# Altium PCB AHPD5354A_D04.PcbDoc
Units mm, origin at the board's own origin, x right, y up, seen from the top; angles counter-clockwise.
Board outline 70.4 x 70.4 mm, 2 copper layers (Top Layer, Bottom Layer), stack 1.57 mm thick; 18 components, 11 nets, 81 pads, 300 vias.
Unrouted connection lines stored in the file: 6.
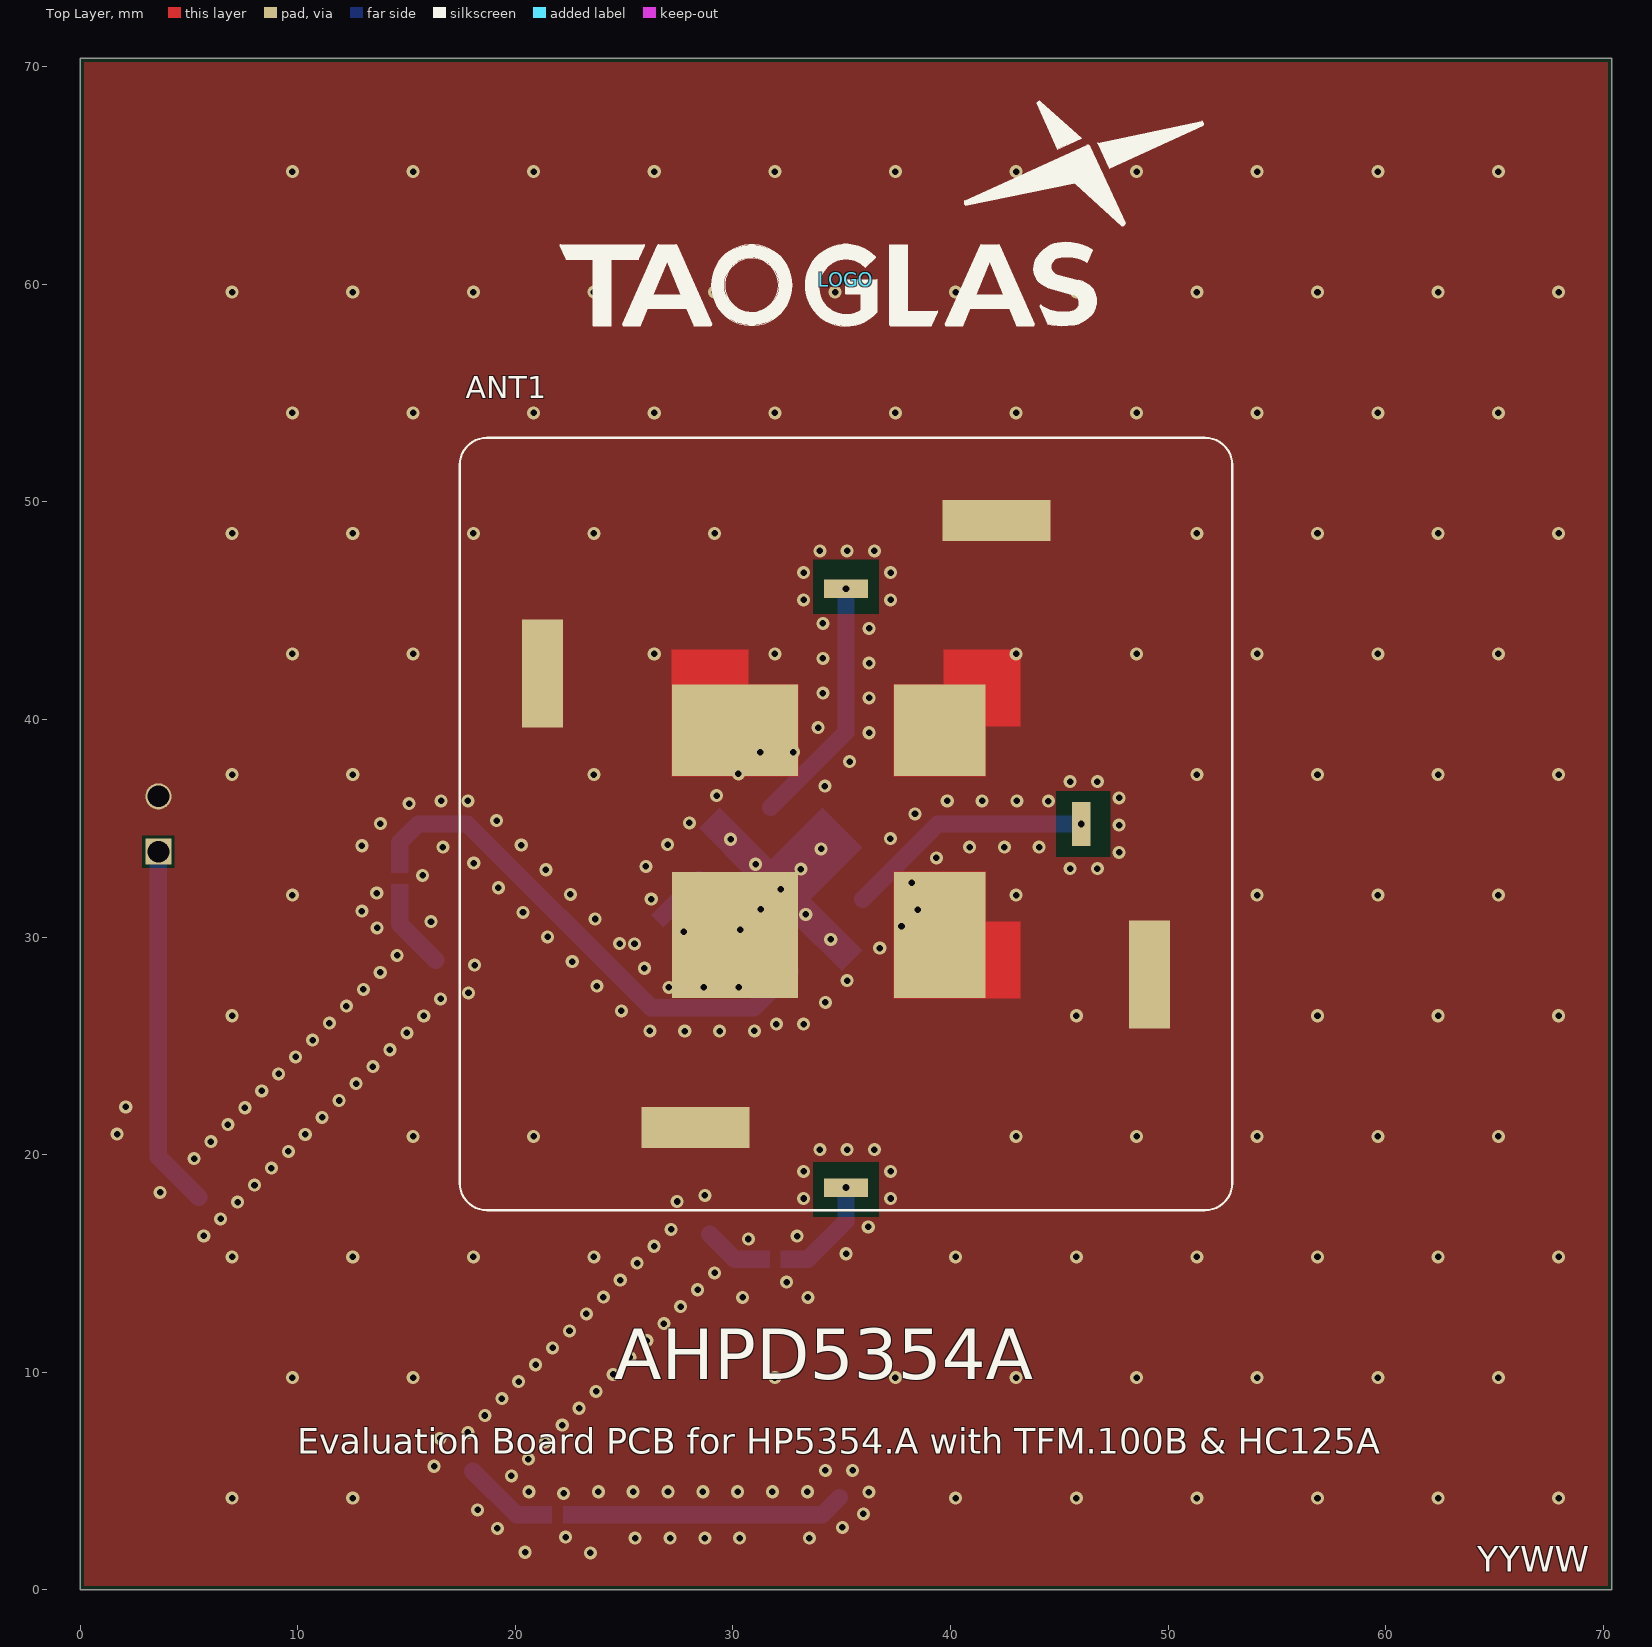
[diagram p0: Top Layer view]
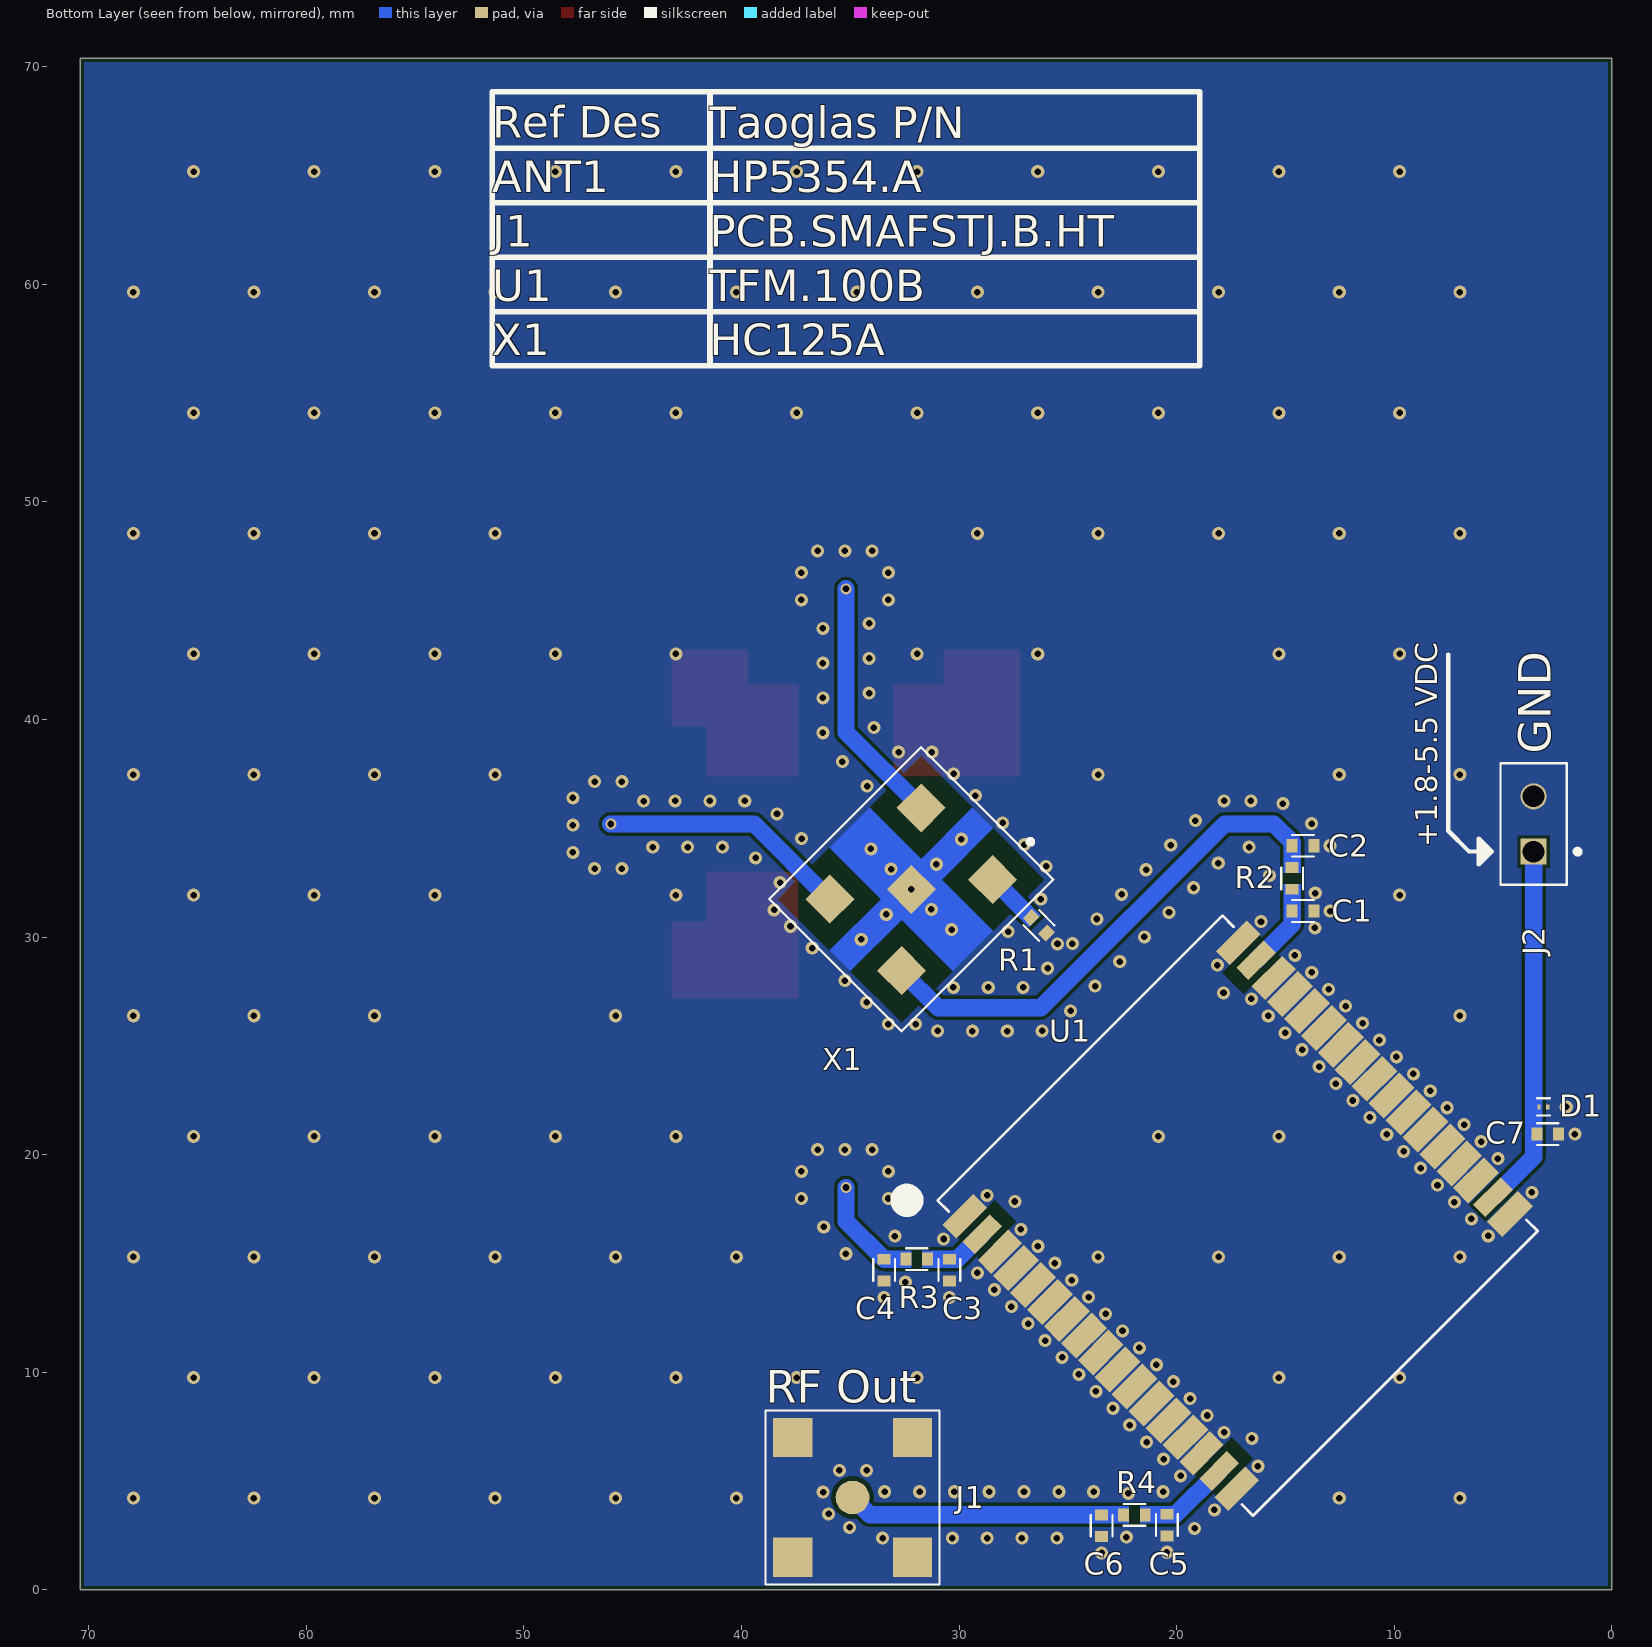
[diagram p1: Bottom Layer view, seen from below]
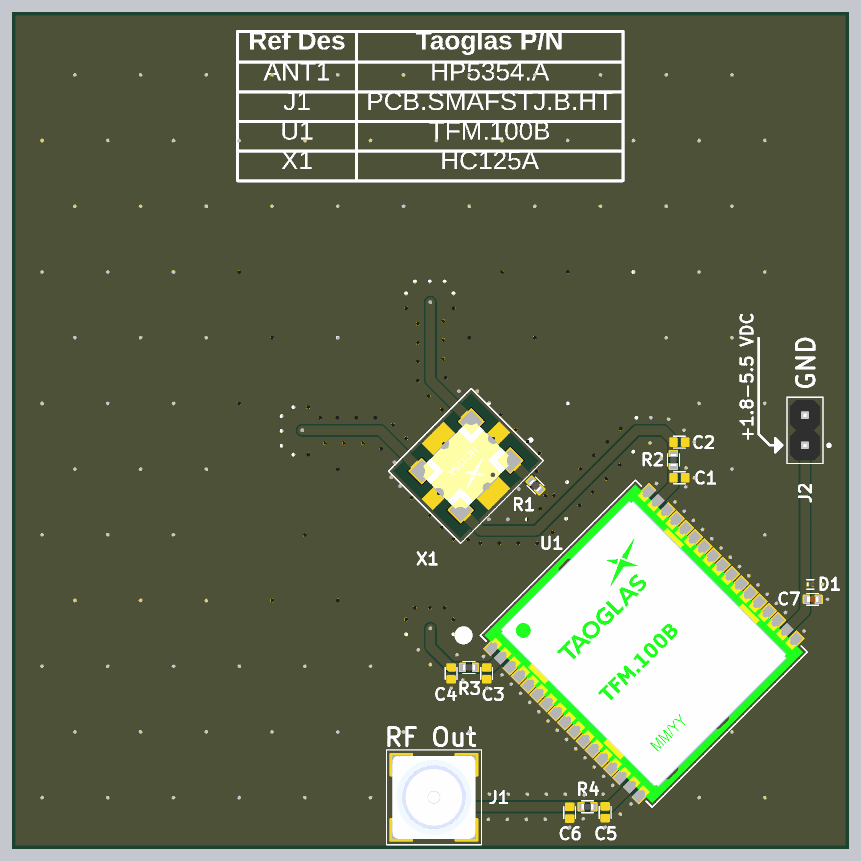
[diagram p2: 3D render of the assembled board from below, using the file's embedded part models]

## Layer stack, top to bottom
Top Solder Mask: solder mask 0.01, Solder Resist, Dk 3.5
Top Layer: signal copper 0.035
Dielectric: core 1.5, FR-4, Dk 4.2
Bottom Layer: signal copper 0.035
Bottom Solder Mask: solder mask 0.01, Solder Resist, Dk 3.5

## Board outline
0,0 70.4,0 70.4,70.4 0,70.4

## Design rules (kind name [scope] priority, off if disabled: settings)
BoardOutlineClearance [All] p1: gap=0.196 ignorepadtopadclearanceinfootprint=FALSE
Clearance Clearance_Polygon [All] p1: gap=0.14 ignorepadtopadclearanceinfootprint=FALSE except(0.05: Arc-Arc Arc-Track Track-Track; 0.1: Arc-SMDPad Arc-THPad Track-SMDPad Track-THPad SMDPad-SMDPad SMDPad-THPad THPad-THPad; 0.2: Arc-Via Arc-Text Arc-Hole Track-Via Track-Text Track-Hole SMDPad-Via SMDPad-Text SMDPad-Hole THPad-Via THPad-Text THPad-Hole Via-Via Via-Text Via-Hole Fill-Text Fill-Hole Poly-Text Poly-Hole Region-Text Region-Hole Text-Text Text-Hole)
HoleSize [All] p1: absolutevalues=TRUE maxlimit=6 minlimit=0.15 maxpercent=80.000 minpercent=20.000
MinimumAnnularRing [All] p1: minimumring=0.1
MinimumSolderMaskSliver [All vs InPadClass('All Pads')] p1: minsoldermaskwidth=0.05
PolygonConnect [All] p1: connectstyle=Direct reliefconductorwidth=0.254 reliefentries=4 polygonreliefangle="90 Angle" airgapwidth=0.254
RoutingVias [All] p1: holewidth=0.3 width=0.8 viastyle="Through Hole" minholewidth=0.15 minwidth=0.65 maxholewidth=6 maxwidth=6.5
SilkToSilkClearance [All] p1: silktosilkclearance=0.1
SilkToSolderMaskClearance [IsPad or IsVia vs OnLayer('Top Overlay')] p1: minsilkscreentomaskgap=0.05 clearancetoexposedcopper=FALSE
SilkToSolderMaskClearance SilkToSolderMaskClearance_1 [IsPad or IsVia vs OnLayer('Bottom Overlay')] p2: minsilkscreentomaskgap=0.05 clearancetoexposedcopper=FALSE
SolderMaskExpansion [Not IsVia] p1: expansion=0.1 istentingtop=FALSE
Width [All] p1: maxlimit=5 minlimit=0.1 preferedwidth=1 minimp=50.000000 maximp=50.000000 favimp=50.000000
26 further rules are at their usual default settings.

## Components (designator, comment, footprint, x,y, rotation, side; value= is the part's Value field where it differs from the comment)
ANT1 "TAOGLAS_HP5354.A" TAOGLAS_HP5354.A 35.2,35.2 r0 top
C1 "DNF" "0402 - DNF" 14.2,31.2 r0 bottom
C2 "DNF" "0402 - DNF" 14.2,34.2 r180 bottom
C3 "DNF" "0402 - DNF" 30.45,14.7 r90 bottom
C4 "DNF" "0402 - DNF" 33.45,14.7 r90 bottom
C5 "DNF" "0402 - DNF" 20.453,2.982 r90 bottom
C6 "DNF" "0402 - DNF" 23.45,2.95 r90 bottom
C7 "Capacitor_Ceramic_1005(0402)_L1_W0.5_H0.5mm_100pF+-5%_50V_-55 to 125C_Murata_GRM1555C1H101JA01" "Capacitor - 0402 - GRM" 2.95,20.95 r0 bottom value=100pF
D1 "ESD245B1W0201E6327XTSA1" "Diode - 0201 (0603 Metric) - DSN0603-2" 3.15,22.2 r180 bottom
J1 "TAOGLAS_PCB.SMAFSTJ.B.HT" TAOGLAS_PCB.SMAFSTJ.B.HT 34.9,4.25 r90 bottom
J2 "PREC002SAAN-RC" SULLINS_PREC002SAAN-RC 3.6,35.2 r90 bottom
LOGO "TAOGLAS_LOGO" "TAOGLAS_LOGO - No R - 10.3mm" 35.2,60.2 r0 top
R1 "Resistor_Thick Film_1005(0402)_49.9Ohms+-1%_0.063W" "Resistor - 0402 - RC_L" 26.335,30.545 r45 bottom value=49.9
R2 "Resistor_Thick Film_1005(0402)_0Ohm" "Resistor - 0402 - RC_L" 14.7,32.7 r90 bottom value=0
R3 "Resistor_Thick Film_1005(0402)_0Ohm" "Resistor - 0402 - RC_L" 31.95,15.2 r0 bottom value=0
R4 "Resistor_Thick Film_1005(0402)_0Ohm" "Resistor - 0402 - RC_L" 21.95,3.45 r180 bottom value=0
U1 "TAOGLAS_TFM.100B" TAOGLAS_TFM.100B 17.2,17.2 r135 bottom
X1 "TAOGLAS_HC125A" TAOGLAS_HC125A 32.2,32.2 r315 bottom

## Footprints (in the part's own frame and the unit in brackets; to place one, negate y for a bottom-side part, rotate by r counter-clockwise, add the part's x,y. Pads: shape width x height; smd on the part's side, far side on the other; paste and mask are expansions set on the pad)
"0402 - DNF" [mm]
  rect 0.5x0.6 smd paste-2539.97 mask+0.1: 1(-0.5,0) 2(0.5,0)
  silkscreen extent -0.5,-0.5 0.5,0.5
"Capacitor - 0402 - GRM" [mm]
  rect 0.5x0.6 smd mask+0.1: 1(-0.5,0) 2(0.5,0)
  silkscreen extent -0.5,-0.5 0.5,0.5, body extent -0.5,-0.25 0.5,0.25, height 0.55
"Diode - 0201 (0603 Metric) - DSN0603-2" [mm]
  rect 0.14x0.24 smd paste-2539.97 mask+0.05: 1(-0.2,0) 2(0.2,0)
  silkscreen extent -0.3,-0.4 0.3,0.4, body extent -0.3,-0.15 0.3,0.15, height 0.32
"Resistor - 0402 - RC_L" [mm]
  rect 0.5x0.6 smd mask+0.1: 1(-0.5,0) 2(0.5,0)
  silkscreen extent -0.5,-0.5 0.5,0.5, body extent -0.5,-0.25 0.5,0.25, height 0.4
SULLINS_PREC002SAAN-RC [mm] "2 Positions Header, 0.100\" (2.54mm)"
  rect 1.2x1.2 hole 1 mask+0.1: 1(-1.27,0)
  round 1.2 hole 1 mask+0.1: 2(1.27,0)
  silkscreen extent -2.79,-1.52 2.79,1.52, body extent -2.54,-1.27 2.54,1.27, height 8.38
TAOGLAS_HC125A [mm] "Low Profile, High Performance Multiband GNSS Hybrid Coupler"
  rect 1.6x1.6 smd paste-0.1 mask+0.1: 1(-2.96,2.325) 2(2.96,2.325) 3(2.96,-2.325) 4(-2.96,-2.325)
  rect 1.6x1.6 smd: 5(0,0)
  Top Layer region: -4.62,0.665 -4.62,-0.665 -1.3,-0.665 -1.3,-3.985 1.3,-3.985 1.3,-0.665 4.62,-0.665 4.62,0.665 1.3,0.665 1.3,3.985 -1.3,3.985 -1.3,0.665
  silkscreen extent -5.51,-4.3 4.94,4.3, body extent -3.17,-2.54 3.18,2.54, height 1.5
TAOGLAS_HP5354.A [mm] "Multi-Band GNSS L1/L5 Patch Antenna"
  rect 2x0.85 smd paste-0.1 mask+0.1: 1(0,10.805) 11(0,-16.705)
  rect 0.85x2 smd paste-0.1 mask+0.1: 2(10.805,0)
  rect 5.8x4.2 smd paste-2539.97 mask+0.1: 3(-5.1,4.3)
  rect 4.2x4.2 smd paste-2539.97 mask+0.1: 4(4.3,4.3)
  rect 5.8x5.8 smd paste-0.1 mask+0: 5(-5.1,-5.1)
  rect 4.2x5.8 smd paste-2539.97 mask+0.1: 6(4.3,-5.1)
  rect 4.95x1.9 smd paste-0.1 mask+0: 7(6.915,13.95) 9(-6.915,-13.95)
  rect 1.9x4.95 smd paste-0.1 mask+0: 8(13.95,-6.915) 10(-13.95,6.915)
  Top Layer region: 2.2,2.2 2.2,6.4 4.5,6.4 4.5,8 8,8 8,4.5 6.4,4.5 6.4,2.2
  Top Layer region: -2.2,2.2 -2.2,6.4 -4.5,6.4 -4.5,8 -8,8 -8,2.2
  Top Layer region: 6.4,-2.2 2.2,-2.2 2.2,-8 8,-8 8,-4.5 6.4,-4.5
  silkscreen extent -17.75,-17.75 17.75,17.75, body extent -17.5,-17.51 17.5,17.5, height 4.02
"TAOGLAS_LOGO - No R - 10.3mm" [mm] "Total Height from bottom of the text to the top of the star is 10.3mm"
  silkscreen extent -13.15,-2.12 16.43,8.2
TAOGLAS_PCB.SMAFSTJ.B.HT [mm] "SMA (F) Surface Mount PCB Jack"
  round 1.55 smd paste-0.1 mask+0.1: 1(0,0)
  rect 1.8x1.8 smd paste-0.1 mask+0.1: 2(-2.75,2.75) 3(2.75,2.75) 4(-2.75,-2.75) 5(2.75,-2.75)
  silkscreen extent -4,-4 4,4, body extent -3.5,-3.5 3.5,3.5, height 10.23
TAOGLAS_TFM.100B [mm] "Surface mount GNSS front-end module covering L1/L5"
  rect 2x0.9 smd paste-2539.97 mask+0: 1(-8.9,8.85) 3(-8.9,6.55) 15(-8.9,-6.55) 17(-8.9,-8.85) 32(8.9,6.55) 34(8.9,8.85)
  rect 1.8x0.8 smd paste-2539.97: 2(-8.9,7.7) 16(-8.9,-7.7) 19(8.9,-7.7) 33(8.9,7.7)
  rect 2x1 smd paste-2539.97 mask+0: 4(-8.9,5.5) 5(-8.9,4.4) 6(-8.9,3.3) 7(-8.9,2.2) 8(-8.9,1.1) 9(-8.9,0) 10(-8.9,-1.1) 11(-8.9,-2.2) 12(-8.9,-3.3) 13(-8.9,-4.4) 14(-8.9,-5.5) 18(8.9,-8.8) 20(8.9,-6.6) 21(8.9,-5.5) 22(8.9,-4.4) 23(8.9,-3.3) 24(8.9,-2.2) 25(8.9,-1.1) 26(8.9,0) 27(8.9,1.1) 28(8.9,2.2) 29(8.9,3.3) 30(8.9,4.4) 31(8.9,5.5)
  silkscreen extent -10.5,-10.25 9.25,11.5, body extent -9,-10 9,10, height 2.74

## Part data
ANT1: library part CMP-364-000001-9, "Low Profile Multi-Band GNSS L1/L5 Patch Antenna", Temp_High=+85C, Temp_Low=-40C
C1 C2 C3 C4 C5 C6: library part CMP-00006-21, "Do Not Fit"
C7: library part CMP-001-00343-45, "100 pF ±5% 50V Ceramic Capacitor C0G, NP0 0402 (1005 Metric)", Max. Operating Temperature=125°C, Min. Operating Temperature=-55°C, Package / Case="0402 (1005 Metric)", Temperature Coefficient="C0G, NP0", Tolerance=±5%, Voltage - Rated=50V
D1: library part CMP-004-00167-10, "7.5V Clamp 5.5A (8/20µs) Ipp Tvs Diode Surface Mount WLL-2-3", Capacitance @ Frequency="5.8pF @ 1GHz", Current - Peak Pulse (10/1000µs)="5.5A (8/20µs)", Max. Operating Temperature=125°C, Max. Voltage - Clamping @ Ipp=7.5V, Min. Operating Temperature=-55°C, Package / Case="0201 (0603 Metric)", Power - Peak Pulse=44W, Power Line Protection=No, Supplier Device Package=WLL-2-3, Voltage - Reverse Standoff (Typ)=5.5V
J1: library part CMP-028-000009-10, "SMA (F) Surface Mount PCB Jack", Temp_High=+85C, Temp_Low=-40C
J2: library part CMP-002-00180-7, "Connector Header Through Hole 2 position 0.100\" (2.54mm)", Temp_High=105°C, Temp_Low=-40°C
LOGO: library part CMP-048-000000-2, "Silkscreen Logo - Standard"
R1: library part CMP-009-00330-4, "49.9 Ohms ±1% 0.1W, 1/10W Chip Resistor 0402 (1005 Metric) Automotive AEC-Q200 Thick Film", Max. Operating Temperature=155°C, Min. Operating Temperature=-55°C, Package / Case="0402 (1005 Metric)", Power (Watts)=63mW, Temperature Coefficient=±100ppm/°C, Tolerance=±1%
R2 R3 R4: library part CMP-009-00375-4, "0 Ohms Jumper Chip Resistor 0402 (1005 Metric) Moisture Resistant Thick Film", Max. Operating Temperature=155°C, Min. Operating Temperature=-55°C, Package / Case="0402 (1005 Metric)"
U1: library part CMP-266-000001-10, "Surface mount GNSS front-end module covering L1/L5", Temp_High=+85C, Temp_Low=-40C
X1: library part CMP-002-000151-19, "Low Profile, High Performance Multiband GNSS Hybrid Coupler", Center Frequency=1.39GHz

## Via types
v1: diameter 0.6, hole 0.3, Top Layer to Bottom Layer, tented both sides, 297 vias
v2: diameter 0.5, hole 0.3, Top Layer to Bottom Layer, tented both sides, 3 vias

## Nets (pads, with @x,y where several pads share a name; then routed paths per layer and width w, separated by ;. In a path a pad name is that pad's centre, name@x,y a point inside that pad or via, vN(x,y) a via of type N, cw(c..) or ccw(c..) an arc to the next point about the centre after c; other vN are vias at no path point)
GND: ANT1.3 ANT1.4 ANT1.5 ANT1.6 ANT1.7 ANT1.8 ANT1.9 ANT1.10 C1.1 C2.2 C3.1 C4.1 C5.1 C6.1 C7.1 D1.2 J1.2 J1.3 J1.4 J1.5 J2.2 R1.1 U1.1 U1.3 U1.4 U1.5 U1.6 U1.7 U1.8 U1.9 U1.10 U1.11 U1.12 U1.13 U1.14 U1.15 U1.17 U1.18 U1.20 U1.21 U1.22 U1.23 U1.24 U1.25 U1.26 U1.27 U1.28 U1.29 U1.30 U1.31 U1.32 U1.34 X1.5
  other v1: 23.45,1.7 20.453,1.732 25.513,2.387 27.113,2.387 28.713,2.387 30.313,2.387 33.513,2.387 22.313,2.431 19.177,2.83 35.034,2.881 36,3.5 18.271,3.684 6.99,4.219 12.532,4.219 40.242,4.219 45.784,4.219 51.326,4.219 56.868,4.219 62.41,4.219 67.952,4.219 22.222,4.442 36.25,4.5 20.624,4.513 23.821,4.513 25.421,4.513 27.021,4.513 28.621,4.513 30.221,4.513 31.821,4.513 33.421,4.513 19.826,5.24 34.25,5.5 35.5,5.5 16.271,5.684 20.604,6.018 21.382,6.795 16.549,6.962 17.826,7.24 22.16,7.573 18.604,8.018 22.938,8.351 19.382,8.795 23.715,9.129 20.16,9.573 9.761,9.761 15.303,9.761 31.929,9.761 37.471,9.761 43.013,9.761 48.555,9.761 54.097,9.761 59.639,9.761 65.181,9.761 24.493,9.907 20.938,10.351 25.271,10.685 21.715,11.129 26.049,11.462 22.493,11.907 26.827,12.24 23.271,12.685 27.605,13.018 24.049,13.462 30.45,13.45 33.45,13.45 28.382,13.796 32.467,14.15 24.827,14.24 29.16,14.574 25.605,15.018 6.99,15.303 12.532,15.303 18.074,15.303 23.616,15.303 40.242,15.303 45.784,15.303 51.326,15.303 56.868,15.303 62.41,15.303 67.952,15.303 35.204,15.45 26.382,15.796 30.716,16.129 5.684,16.271 32.954,16.263 27.16,16.574 36.223,16.683 6.462,17.049 7.24,17.826 27.438,17.851 33.25,17.99 37.25,17.99 28.716,18.129 3.684,18.271 8.018,18.604 33.25,19.24 37.25,19.24 8.795,19.382 5.24,19.826 9.573,20.16 34,20.24 35.25,20.24 36.5,20.24 6.018,20.604 15.303,20.845 20.845,20.845 43.013,20.845 48.555,20.845 54.097,20.845 59.639,20.845 65.181,20.845 1.7,20.95 10.351,20.938 6.795,21.382 11.129,21.715 7.573,22.16 2.1,22.2 11.907,22.493 8.351,22.938 12.685,23.271 9.129,23.715 13.462,24.049 9.907,24.493 14.24,24.827 10.685,25.271 15.018,25.605 26.189,25.692 27.789,25.687 29.389,25.687 30.989,25.689 32,26 33.25,26 11.462,26.049 6.99,26.387 15.796,26.382 45.784,26.387 56.868,26.387 62.41,26.387 67.952,26.387 24.882,26.614 12.24,26.827 34.25,27 16.574,27.16 17.851,27.438 13.018,27.605 27.063,27.69 28.663,27.69 30.263,27.69 23.75,27.746 35.25,28 13.796,28.382 25.932,28.572 18.129,28.716 22.619,28.877 14.574,29.16 36.75,29.5 25.481,29.692 24.801,29.703 34.498,29.902 21.488,30.008 27.75,30.25 30.344,30.344 13.656,30.428 37.75,30.5 16.129,30.716 23.669,30.835 33.349,31.051 20.356,31.14 12.95,31.2 31.272,31.272 38.5,31.25 26.25,31.75 9.761,31.929 43.013,31.929 54.097,31.929 59.639,31.929 65.181,31.929 22.538,31.966 13.637,32.028 32.2,32.2 19.225,32.271 38.226,32.511 15.741,32.835 21.407,33.097 33.128,33.128 45.5,33.15 46.75,33.15 26,33.25 31.051,33.349 18.093,33.403 39.358,33.642 47.75,33.9 34.056,34.056 16.672,34.137 40.88,34.137 42.48,34.137 44.08,34.137 12.95,34.2 20.275,34.229 27,34.25 29.902,34.498 37.239,34.531 47.75,35.15 13.807,35.214 28,35.25 19.144,35.36 38.37,35.663 15.121,36.137 44.5,36.25 16.597,36.263 17.821,36.261 39.853,36.263 41.453,36.263 43.053,36.263 47.75,36.4 29.25,36.5 34.23,36.938 45.5,37.15 46.75,37.15 6.99,37.471 12.532,37.471 23.616,37.471 51.326,37.471 56.868,37.471 62.41,37.471 67.952,37.471 30.25,37.5 35.362,38.069 31.25,38.5 32.783,38.499 36.261,39.393 33.915,39.63 36.263,40.993 34.137,41.215 36.263,42.593 34.137,42.815 9.761,43.013 15.303,43.013 26.387,43.013 31.929,43.013 43.013,43.013 48.555,43.013 54.097,43.013 59.639,43.013 65.181,43.013 36.263,44.193 34.137,44.415 33.25,45.5 37.25,45.5 33.25,46.75 37.25,46.75 34,47.75 35.25,47.75 36.5,47.75 6.99,48.555 12.532,48.555 18.074,48.555 23.616,48.555 29.158,48.555 51.326,48.555 56.868,48.555 62.41,48.555 67.952,48.555 9.761,54.097 15.303,54.097 20.845,54.097 26.387,54.097 31.929,54.097 37.471,54.097 43.013,54.097 48.555,54.097 54.097,54.097 59.639,54.097 65.181,54.097 6.99,59.639 12.532,59.639 18.074,59.639 23.616,59.639 29.158,59.639 34.7,59.639 40.242,59.639 45.784,59.639 51.326,59.639 56.868,59.639 62.41,59.639 67.952,59.639 9.761,65.181 15.303,65.181 20.845,65.181 26.387,65.181 31.929,65.181 37.471,65.181 43.013,65.181 48.555,65.181 54.097,65.181 59.639,65.181 65.181,65.181
NetANT1_1: ANT1.1 X1.4 | length 11.5
  Bottom Layer w0.8: X1.4@31.751,35.963 35.2,39.412 v2(35.2,46.005)
NetANT1_2: ANT1.2 X1.3 | length 11.5
  Bottom Layer w0.8: X1.3@35.963,31.751 39.412,35.2 v2(46.005,35.2)
NetANT1_11: ANT1.11 C4.2 R3.2 | length 4.9
  Bottom Layer w0.8: R3.2@32.6,15.2 C4.2 35.2,16.95 v2(35.2,18.495)
NetC1_2: C1.2 R2.1 U1.33 | length 3.8
  Bottom Layer w0.8: R2.1@14.7,32.05 14.7,30.589 U1.33
NetC2_1: C2.1 R2.2 X1.2 | length 23.5
  Bottom Layer w0.8: R2.2@14.7,33.35 14.7,34.364 15.536,35.2 17.8,35.2 26.25,26.75 30.962,26.75 X1.2@32.649,28.438
NetC3_2: C3.2 R3.1 U1.2 | length 2.8
  Bottom Layer w0.8: U1.2 30.089,15.2 R3.1@31.3,15.2
NetC5_2: C5.2 R4.2 U1.16 | length 4.1
  Bottom Layer w0.8: U1.16 20.061,3.45 R4.2@21.3,3.45
NetC6_2: C6.2 J1.1 R4.1 | length 12.6
  Bottom Layer w0.8: R4.1@22.6,3.45 C6.2 34.1,3.45 J1.1
NetC7_2: C7.2 D1.1 J2.1 U1.19 | length 16.7
  Bottom Layer w0.8: J2.1 3.6,19.911 U1.19
NetR1_2: R1.2 X1.1 | length 2.3
  Bottom Layer w0.8: R1.2@26.794,31.005 X1.1@28.438,32.649

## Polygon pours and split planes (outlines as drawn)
GND on Top Layer "GND_L01_P000" (solid, remove dead copper, pour order 0): 0,0 0,70.4 70.4,70.4 70.4,0
GND on Bottom Layer "GND_L02_P000" (solid, remove dead copper, pour order 1): 0,0 0,70.4 70.4,70.4 70.4,0

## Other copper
Top Layer:
  pour cut-out: 44.855,33.7 47.355,33.7 47.355,36.7 44.855,36.7
  pour cut-out: 36.7,44.855 36.7,47.355 33.7,47.355 33.7,44.855
  pour cut-out: 33.7,19.645 33.7,17.145 36.7,17.145 36.7,19.645
  text ".Layer_Name" at -47.55,53.284 h2
Bottom Layer:
  region net NetR1_2: 26.794,30.439 27.36,31.005 26.794,31.571 26.228,31.005
  rectangle net NetC1_2: 14.3,31.65 15.1,32.45
  rectangle net NetC2_1: 14.3,32.95 15.1,33.75
  rectangle net NetANT1_11: 32.2,14.8 33,15.6
  rectangle net NetC3_2: 30.9,14.8 31.7,15.6
  rectangle net NetC6_2: 22.2,3.05 23,3.85
  rectangle net NetC5_2: 20.9,3.05 21.7,3.85
  pour cut-out: 35.875,4.25 cw(c34.9,4.25) 34.9,3.275 cw(c34.9,4.25) 33.925,4.25 cw(c34.9,4.25) 34.9,5.225 cw(c34.9,4.25)
  pour cut-out: 30.896,15.751 33.004,15.751 33.004,14.649 30.896,14.649
  pour cut-out: 16.493,6.028 17.483,7.018 19.18,5.321 18.19,4.331
  pour cut-out: 27.382,16.917 28.372,17.907 30.069,16.21 29.079,15.22
  pour cut-out: 15.22,29.079 16.21,30.069 17.907,28.372 16.917,27.382
  pour cut-out: 25.999,31.005 26.114,31.12 26.909,30.325 26.794,30.21
  pour cut-out: 15.251,33.754 15.251,31.646 14.149,31.646 14.149,33.754
  pour cut-out: 20.896,4.001 23.004,4.001 23.004,2.899 20.896,2.899
  pour cut-out: 35.962,34.102 38.314,31.751 35.962,29.4 33.611,31.751
  pour cut-out: 35,28.438 32.649,26.086 30.298,28.438 32.649,30.789
  pour cut-out: 28.438,30.298 26.086,32.649 28.438,35.001 30.789,32.649
  pour cut-out: 29.4,35.962 31.751,38.314 34.102,35.962 31.751,33.611
  text ".Layer_Name" at -47.55,48.284 h2

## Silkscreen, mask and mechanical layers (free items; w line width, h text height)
Top Overlay:
  region: 194.973,23.562 194.973,24.015
  text ".Layer_Name" at -47.55,43.284 h2
  text "AHPD5354A" at 24.546,8.891 h4
  text "Evaluation Board PCB for HP5354.A with TFM.100B & HC125A" at 9.982,5.862 h2
  text "YYWW" at 64.204,0.45 h2
Bottom Overlay:
  circle w0.25: c1.58,33.93 r0.1
  region: 5.961,33.701 5.961,34.154 5.676,34.154 5.676,33.701
  region: 6.181,33.529 6.181,34.34 5.853,34.34 5.853,33.529
  lines w0.2: 5.608,33.936 6.57,33.936 7.519,34.885 7.519,42.987 ; 5.522,33.936 6.119,34.533 6.119,33.339 5.522,33.936
  lines w0.254: 18.95,58.75 51.45,58.75 ; 18.95,61.25 51.45,61.25 ; 18.95,63.75 51.45,63.75 ; 18.95,66.25 51.45,66.25 ; 41.45,56.25 41.45,68.85 ; 18.95,56.25 51.45,56.25 51.45,68.85 18.95,68.85 18.95,56.25
  text "Ref Des" at 51.45,66.25 h2.5
  text "Taoglas P/N" at 41.45,66.229 h2.5
  text "HP5354.A" at 41.45,63.75 h2.5
  text "ANT1" at 51.45,63.75 h2.5
  text "PCB.SMAFSTJ.B.HT" at 41.45,61.25 h2.5
  text "J1" at 51.45,61.25 h2.5
  text "TFM.100B" at 41.45,58.75 h2.5
  text "U1" at 51.45,58.75 h2.5
  text "HC125A" at 41.45,56.25 h2.5
  text "X1" at 51.45,56.25 h2.5
  text "GND" at 2.822,38.436 h1.5 r270
  text ".Layer_Name" at -47.55,38.284 h2
  text "+1.8-5.5 VDC" at 8.022,34.138 h1 r270
  text "RF Out" at 38.899,8.6 h1.5
Top Paste:
  text ".Layer_Name" at -47.55,23.284 h2
Bottom Paste:
  text ".Layer_Name" at -47.55,17.95 h2
Top Solder Mask:
  text ".Layer_Name" at -47.55,33.284 h2
Bottom Solder Mask:
  text ".Layer_Name" at -47.55,27.95 h2
Board Outline:
  the board outline again, w0.2
  text ".Layer_Name" at -47.55,57.95 h2
Top Assembly:
  lines w0.1: 38.95,46.25 40.55,46.25
  text ".Layer_Name" at -47.55,13.284 h2
Bottom Assembly:
  text ".Layer_Name" at -47.55,8.284 h2
IDW (Mech7):
  drawing of 191 lines, arcs and shapes, not listed
  text "Layer" at -28.427,-16.998 h1.52
  text "Name" at -18.016,-16.998 h1.52
  text "Material" at 11.44,-16.998 h1.52
  text "Thickness" at 33.278,-16.998 h1.52
  text "Constant" at 49.784,-16.998 h1.52
  text "Board Layer Stack" at 64.258,-16.998 h1.52
  text "Top Overlay" at -18.016,-20.046 h1.52
  text "Top Solder Mask" at -18.016,-23.094 h1.52
  text "Solder Resist" at 11.44,-23.094 h1.52
  text "0.010mm" at 33.278,-23.094 h1.52
  text "3.5" at 49.784,-23.094 h1.52
  text "1" at -28.427,-26.142 h1.52
  text "Top Layer" at -18.016,-26.142 h1.52
  text "0.035mm" at 33.278,-26.142 h1.52
  text "Dielectric" at -18.016,-29.19 h1.52
  text "FR-4" at 11.44,-29.19 h1.52
  text "1.500mm" at 33.278,-29.19 h1.52
  text "4.2" at 49.784,-29.19 h1.52
  text "2" at -28.427,-32.238 h1.52
  text "Bottom Layer" at -18.016,-32.238 h1.52
  text "0.035mm" at 33.278,-32.238 h1.52
  text "Bottom Solder Mask" at -18.016,-35.286 h1.52
  text "Solder Resist" at 11.44,-35.286 h1.52
  text "0.010mm" at 33.278,-35.286 h1.52
  text "3.5" at 49.784,-35.286 h1.52
  text "Bottom Overlay" at -18.016,-38.334 h1.52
